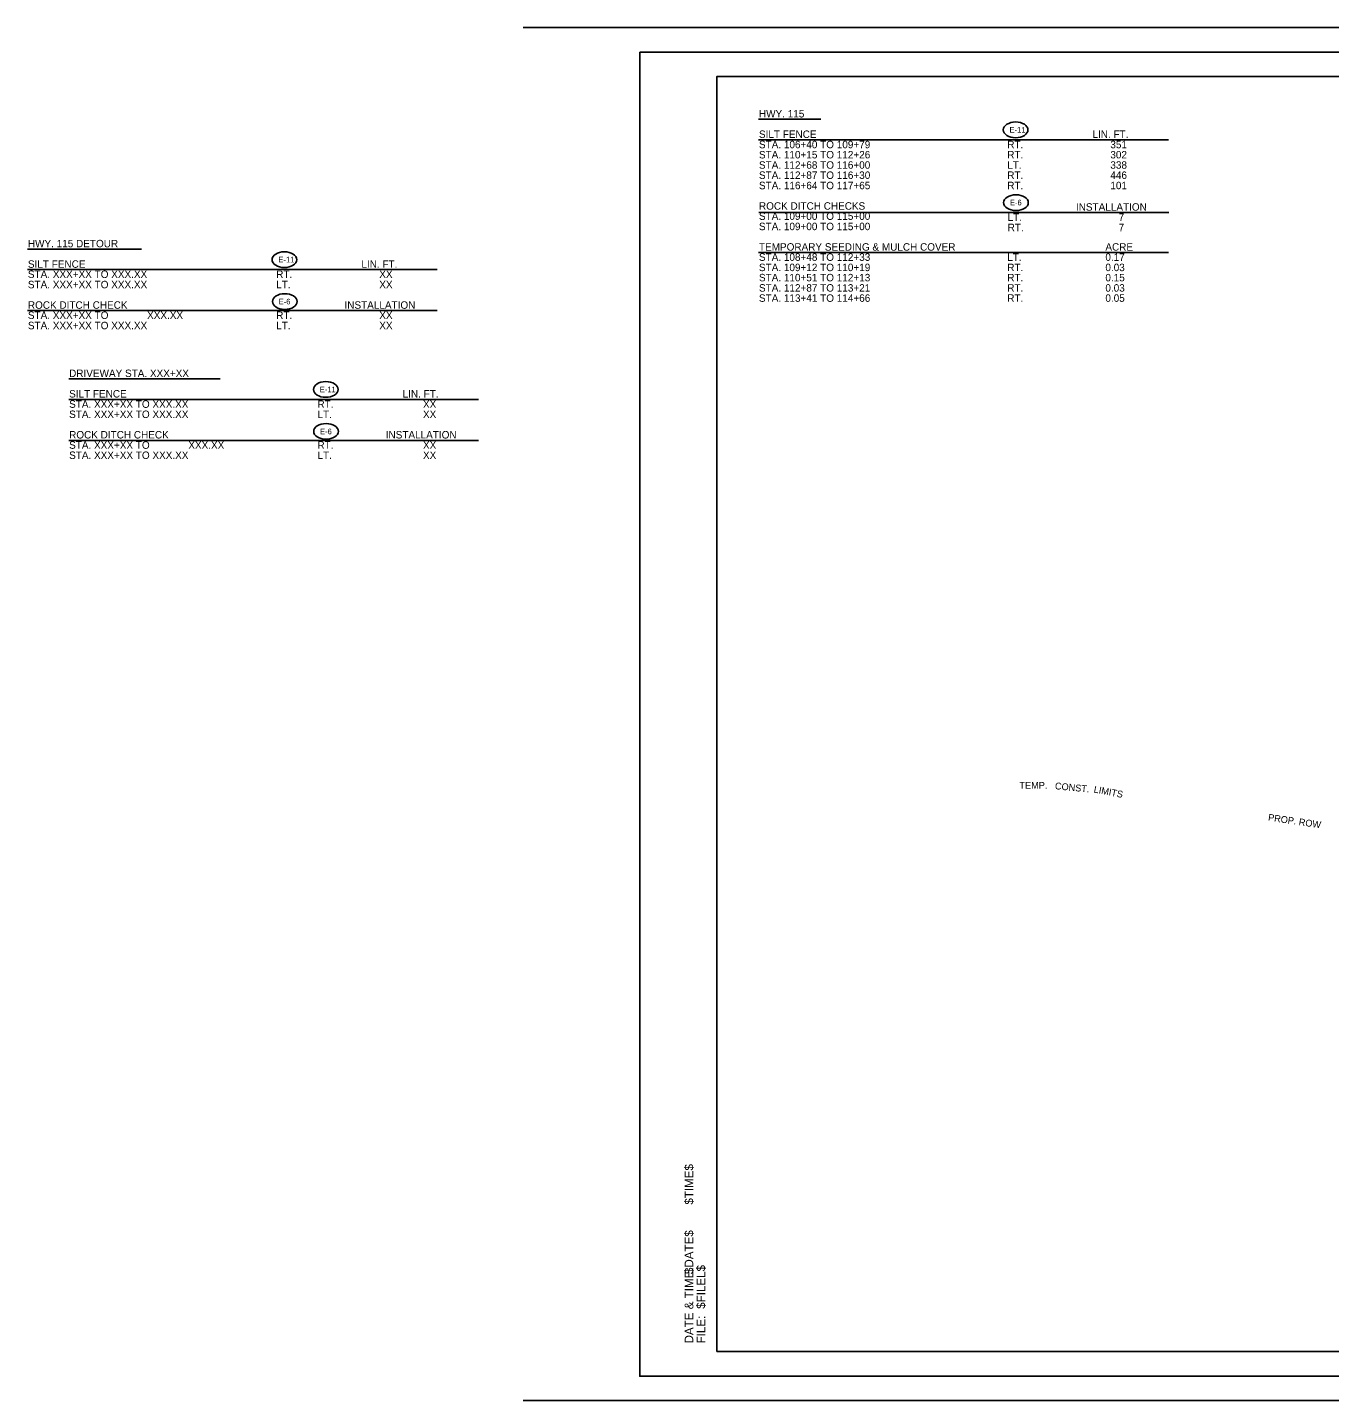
# Model space of a CAD drawing. Extents: x 7675 to 14104, y 9961 to 11168.
# Drawn here: x 7675 to 8724, y 9961 to 11067 of the extents above; entities that cross this region are included whole.
import ezdxf

# ---------------------------------------------------------------- set-up
doc = ezdxf.new("R2010")
doc.units = 0
for name, color, linetype in [('GREEN_TXT', 7, 'Continuous'), ('R_ROW Annot Labels Ends', 7, 'Continuous'), ('SEAL-INFO', 7, 'Continuous'), ('Stage 1 Ditch Checks', 7, 'Continuous'), ('Stage 2 Construction', 7, 'Continuous'), ('Stage 2 Flow Arrows', 7, 'Continuous')]:
    doc.layers.add(name, color=color, linetype=linetype)

msp = doc.modelspace()

# ---------------------------------------------------------------- linework, layer by layer
at = {"layer": 'GREEN_TXT'}
for p, q in [((9834.6, 11066.7), (8074.6, 11066.7)), ((8230.7, 11027.3), (9811.6, 11027.3)), ((8230.7, 10000), (8230.7, 11027.3)), ((9811.6, 10000), (8230.7, 10000)), ((8074.6, 9960.6), (9834.6, 9960.6))]:
    msp.add_line(p, q, dxfattribs=at)
at = {"layer": 'SEAL-INFO'}
msp.add_lwpolyline([(8168.6, 11046.8), (9835.3, 11046.8), (9835.3, 9980.1), (8168.6, 9980.1)], close=True, dxfattribs=at)
at = {"layer": 'Stage 1 Ditch Checks'}
msp.add_lwpolyline([(8230.7, 10000), (9811.6, 10000), (9811, 10963.3), (9596.1, 10963.3), (9588, 10959.9), (9579.2, 10961.4), (9578.9, 10977.9), (9400.3, 10977.9), (9400.3, 11027.3), (8230.7, 11027.3)], close=True, dxfattribs=at)
msp.add_lwpolyline([(8230.7, 10000), (9811.6, 10000), (9811, 10963.3), (9596.1, 10963.3), (9588, 10959.9), (9579.2, 10961.4), (9578.9, 10977.9), (9400.3, 10977.9), (9400.3, 11027.3), (8230.7, 11027.3)], close=True, dxfattribs=at)
msp.add_lwpolyline([(8230.7, 10000), (9811.6, 10000), (9811, 10963.3), (9596.1, 10963.3), (9588, 10959.9), (9579.2, 10961.4), (9578.9, 10977.9), (9400.3, 10977.9), (9400.3, 11027.3), (8230.7, 11027.3)], close=True, dxfattribs=at)
msp.add_lwpolyline([(8230.7, 10000), (9811.6, 10000), (9811, 10963.3), (9596.1, 10963.3), (9588, 10959.9), (9579.2, 10961.4), (9578.9, 10977.9), (9400.3, 10977.9), (9400.3, 11027.3), (8230.7, 11027.3)], close=True, dxfattribs=at)
msp.add_lwpolyline([(8230.7, 10000), (9811.6, 10000), (9811, 10963.3), (9596.1, 10963.3), (9588, 10959.9), (9579.2, 10961.4), (9578.9, 10977.9), (9400.3, 10977.9), (9400.3, 11027.3), (8230.7, 11027.3)], close=True, dxfattribs=at)
at = {"layer": 'Stage 2 Flow Arrows'}
for p, q in [((8264.3, 10992.7), (8314.3, 10992.7)), ((8264.3, 10976.2), (8594.3, 10976.2)), ((8264.6, 10917.7), (8594.6, 10917.7)), ((7675.4, 10888.2), (7767.4, 10888.2)), ((8264.3, 10885.5), (8594.3, 10885.5)), ((7675.4, 10871.7), (8005.4, 10871.7)), ((7675.4, 10838.7), (8005.4, 10838.7)), ((7708.7, 10783.6), (7830.7, 10783.6)), ((7708.7, 10767.1), (8038.7, 10767.1)), ((7708.7, 10734.1), (8038.7, 10734.1))]:
    msp.add_line(p, q, dxfattribs=at)
for centre in [(8471.3, 10984.2), (8471.6, 10925.6), (7882.4, 10879.6), (7882.7, 10845.9), (7915.7, 10775.1), (7915.9, 10741.3)]:
    msp.add_ellipse(centre, major_axis=(9.94, 0), ratio=0.638788, dxfattribs=at)

# ---------------------------------------------------------------- texts
for s, height, p in [('$TIME$', 6.98, (8211.7, 10118.4)), ('$DATE$', 6.98, (8211.7, 10062.5)), ('DATE & TIME:', 6.984, (8211.7, 10006.6)), ('$FILEL$', 6.98, (8221.3, 10034.5)), ('FILE: ', 6.98, (8221.3, 10006.6))]:
    msp.add_text(s, height=height, rotation=90).set_placement(p)
at = {"layer": 'R_ROW Annot Labels Ends'}
msp.add_text('PROP. ROW', height=5.5, rotation=351.6757, dxfattribs=at).set_placement((8674.4, 10427.8))
at = {"layer": 'Stage 2 Construction'}
for s, rotation, p in [('TEMP. ', 0.0182, (8474.4, 10453.4)), ('CONST. ', 354.4414, (8502.8, 10453.1)), (' LIMITS', 349.1012, (8531.9, 10450.9))]:
    msp.add_text(s, height=5.5, rotation=rotation, dxfattribs=at).set_placement(p)
at = {"layer": 'Stage 2 Flow Arrows'}
for s, height, p in [('HWY. 115', 6, (8264.6, 10994.2)), ('SILT FENCE', 6, (8264.6, 10977.7)), ('E-11', 4.54, (8466.4, 10981.9)), ('LIN. FT.', 6, (8533.2, 10977.7)), ('STA. 106+40 TO 109+79', 6, (8264.6, 10969.4)), ('RT.', 6, (8464.6, 10969.4)), ('351', 6, (8547.6, 10969.4)), ('STA. 110+15 TO 112+26', 6, (8264.6, 10961.2)), ('RT.', 6, (8464.6, 10961.2)), ('302', 6, (8547.6, 10961.2)), ('STA. 112+68 TO 116+00', 6, (8264.6, 10952.9)), ('STA. 112+87 TO 116+30', 6, (8264.6, 10944.7)), ('LT.', 6, (8464.6, 10952.9)), ('RT.', 6, (8464.6, 10944.7)), ('446', 6, (8547.6, 10944.7)), ('338', 6, (8547.6, 10952.9)), ('STA. 116+64 TO 117+65', 6, (8264.6, 10936.4)), ('RT.', 6, (8464.6, 10936.4)), ('101', 6, (8547.6, 10936.4)), ('STA. 109+00 TO 115+00', 6, (8264.6, 10911.7)), ('ROCK DITCH CHECKS', 6, (8264.6, 10919.9)), ('INSTALLATION', 6, (8519.9, 10919.1)), ('STA. 109+00 TO 115+00', 6, (8264.6, 10903.4)), ('LT.', 6, (8464.9, 10910.9)), ('RT.', 6, (8464.9, 10902.6)), ('7', 6, (8554.3, 10910.9)), ('7', 6, (8554.3, 10902.6)), ('HWY. 115 DETOUR', 6, (7675.8, 10889.6)), ('TEMPORARY SEEDING & MULCH COVER', 6, (8264.6, 10886.9)), ('STA. 108+48 TO 112+33', 6, (8264.6, 10878.7)), ('LT.', 6, (8464.6, 10878.7)), ('ACRE', 6, (8543.6, 10886.9)), ('0.17', 6, (8543.6, 10878.7)), ('SILT FENCE', 6, (7675.8, 10873.1)), ('E-11', 4.54, (7877.6, 10877.4)), ('LIN. FT.', 6, (7944.4, 10873.1)), ('STA. 109+12 TO 110+19', 6, (8264.6, 10870.4)), ('RT.', 6, (8464.6, 10870.4)), ('0.03', 6, (8543.6, 10870.4)), ('STA. XXX+XX TO XXX.XX', 6, (7675.8, 10864.9)), ('STA. XXX+XX TO XXX.XX', 6, (7675.8, 10856.6)), ('RT.', 6, (7875.8, 10864.9)), ('LT.', 6, (7875.8, 10856.6)), ('XX', 6, (7958.8, 10864.9)), ('XX', 6, (7958.8, 10856.6)), ('STA. 110+51 TO 112+13', 6, (8264.6, 10862.2)), ('RT.', 6, (8464.6, 10862.2)), ('0.15', 6, (8543.6, 10862.2)), ('STA. 112+87 TO 113+21', 6, (8264.6, 10853.9)), ('STA. 113+41 TO 114+66', 6, (8264.6, 10845.7)), ('RT.', 6, (8464.6, 10853.9)), ('RT.', 6, (8464.6, 10845.7)), ('0.03', 6, (8543.6, 10853.9)), ('0.05', 6, (8543.6, 10845.7)), ('ROCK DITCH CHECK', 6, (7675.8, 10840.1)), ('INSTALLATION', 6, (7930.8, 10840.1)), ('STA. XXX+XX TO', 6, (7675.8, 10831.9)), ('STA. XXX+XX TO XXX.XX', 6, (7675.8, 10823.6)), ('XXX.XX', 6, (7771.8, 10831.9)), ('RT.', 6, (7875.8, 10831.9)), ('LT.', 6, (7875.8, 10823.6)), ('XX', 6, (7958.8, 10831.9)), ('XX', 6, (7958.8, 10823.6)), ('DRIVEWAY STA. XXX+XX', 6, (7709, 10785.1)), ('SILT FENCE', 6, (7709, 10768.6)), ('E-11', 4.54, (7910.9, 10772.8)), ('LIN. FT.', 6, (7977.6, 10768.6)), ('STA. XXX+XX TO XXX.XX', 6, (7709, 10760.3)), ('RT.', 6, (7909, 10760.3)), ('XX', 6, (7994, 10760.3)), ('STA. XXX+XX TO XXX.XX', 6, (7709, 10752.1)), ('LT.', 6, (7909, 10752.1)), ('XX', 6, (7994, 10752.1)), ('ROCK DITCH CHECK', 6, (7709, 10735.6)), ('INSTALLATION', 6, (7964, 10735.6)), ('STA. XXX+XX TO', 6, (7709, 10727.3)), ('XXX.XX', 6, (7805, 10727.3)), ('RT.', 6, (7909, 10727.3)), ('XX', 6, (7994, 10727.3)), ('STA. XXX+XX TO XXX.XX', 6, (7709, 10719.1)), ('LT.', 6, (7909, 10719.1)), ('XX', 6, (7994, 10719.1))]:
    msp.add_text(s, height=height, dxfattribs=at).set_placement(p)
for p in [(8466.7, 10923.4), (7877.8, 10843.6), (7911.1, 10739)]:
    msp.add_text('E-6', height=4.54, rotation=360, dxfattribs=at).set_placement(p)

doc.saveas('drawing.dxf')
